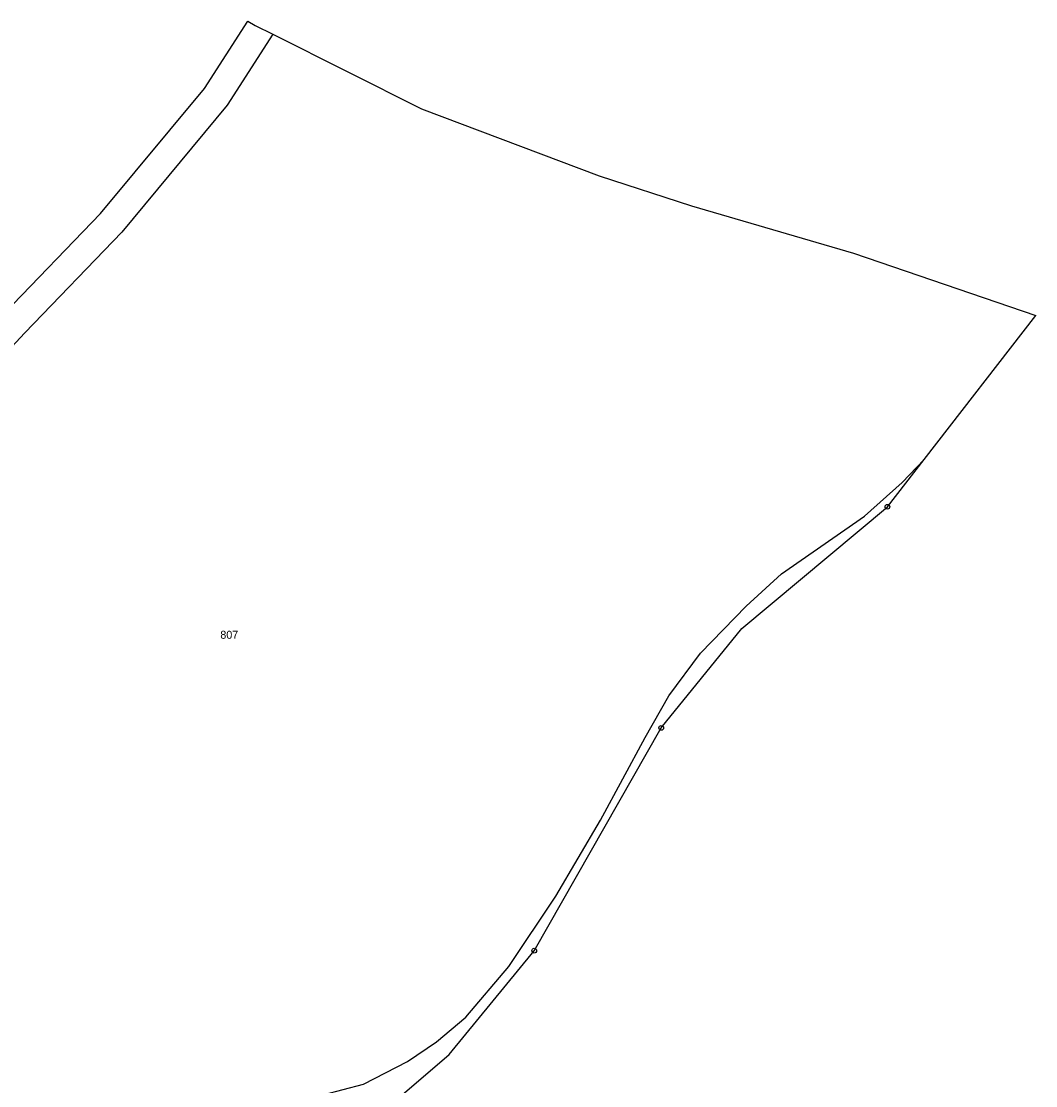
# Model space of a CAD drawing. Extents: x -754445 to -751443, y -1030748 to -1028224.
# Drawn here: x -753188.8 to -752973.3, y -1028567.3 to -1028341.2 of the extents above; entities that cross this region are included whole.
import ezdxf
from ezdxf.enums import TextEntityAlignment as Align

# ---------------------------------------------------------------- set-up
doc = ezdxf.new("R2010")
doc.units = 0
doc.header["$LTSCALE"] = 0.68
doc.layers.add('1', color=7, linetype='Continuous', lineweight=25)
doc.layers.add('8', color=7, linetype='Continuous', lineweight=25)
doc.layers.add('2', color=7, linetype='Continuous')

msp = doc.modelspace()

# ---------------------------------------------------------------- linework, layer by layer
at = {"layer": '1'}
for p, q in [((-753140.7, -1028341.18), (-753139.11, -1028342.06)), ((-753139.11, -1028342.06), (-753135.36, -1028343.94))]:
    msp.add_line(p, q, dxfattribs=at)
for points in [[(-753426.96, -1028564.01), (-753384.18, -1028548.32), (-753359.89, -1028535.3), (-753314.5, -1028507.94), (-753266.22, -1028477.24), (-753245.5, -1028460.32), (-753192.4, -1028403.23), (-753171.93, -1028381.99), (-753149.89, -1028355.48), (-753140.7, -1028341.18)], [(-753135.36, -1028343.94), (-753145.04, -1028359.03), (-753167.46, -1028386), (-753188.04, -1028407.36), (-753241.39, -1028464.71), (-753262.7, -1028482.11), (-753311.34, -1028513.04), (-753325.92, -1028521.83)], [(-753135.36, -1028343.94), (-753103.76, -1028359.79), (-753066.07, -1028374.04), (-753046.45, -1028380.42), (-753012.04, -1028390.43), (-752973.34, -1028403.67)], [(-753124.73, -1028569.25), (-753116.13, -1028566.95), (-753106.77, -1028562.16), (-753100.57, -1028558), (-753094.4, -1028552.73), (-753085.21, -1028541.96), (-753075.26, -1028527.05), (-753065.74, -1028510.91), (-753056.29, -1028493.34), (-753051.24, -1028484.46), (-753044.53, -1028475.42), (-753034.84, -1028465.4), (-753027.3, -1028458.59), (-753009.73, -1028446.31), (-753001.71, -1028439.19), (-752997.06, -1028434.29), (-752973.34, -1028403.67)], [(-753124.11, -1028579.78), (-753109.41, -1028570.52), (-753097.94, -1028560.66), (-753079.85, -1028538.62), (-753052.86, -1028491.28), (-753035.74, -1028470.18), (-753004.82, -1028444.31), (-752997.06, -1028434.29)]]:
    msp.add_lwpolyline(points, dxfattribs=at)
at = {"layer": '8'}
for centre, radius in [((-753004.82, -1028444.3099), 0.5), ((-753004.82, -1028444.3099), 0.0303), ((-753052.86, -1028491.2799), 0.5), ((-753052.86, -1028491.2799), 0.0303), ((-753079.85, -1028538.6199), 0.5), ((-753079.85, -1028538.6199), 0.0303)]:
    msp.add_circle(centre, radius, dxfattribs=at)

# ---------------------------------------------------------------- texts
at = {"layer": '2'}
msp.add_text('807', height=1.7, dxfattribs=at).set_placement((-753144.609, -1028472.356), align=Align.CENTER)

doc.saveas('drawing.dxf')
